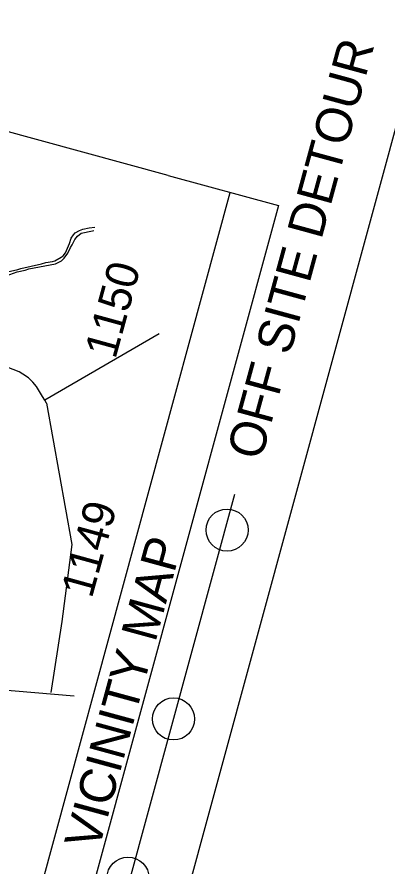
# Model space of a CAD drawing. Extents: x 2076126 to 2079903, y 925480 to 928006.
# Drawn here: x 2078865.6 to 2079033.1, y 926019.2 to 926403.1 of the extents above; entities that cross this region are included whole.
import ezdxf

# ---------------------------------------------------------------- set-up
doc = ezdxf.new("R2010")
doc.units = 0
for name, color, linetype in [('Default', 7, 'Continuous'), ('Old_Level_32', 7, 'Continuous'), ('Old_Level_59', 7, 'Continuous'), ('Old_Level_8', 7, 'Continuous'), ('Prop Roadway Bridge', 7, 'Continuous'), ('Prop Shade Heavy', 7, 'Continuous'), ('Prop Shade Light', 7, 'Continuous'), ('Sheet Title CELL', 7, 'Continuous')]:
    doc.layers.add(name, color=color, linetype=linetype)

msp = doc.modelspace()

# ---------------------------------------------------------------- linework, layer by layer
at = {"layer": 'Default'}
for p, q in [((2078934.09, 926331.41), (2078643.24, 926410.74)), ((2078934.09, 926331.41), (2078983.97, 926317.8)), ((2078845.04, 925894.23), (2078962.19, 926323.74)), ((2078983.97, 926317.8), (2078866.82, 925888.29))]:
    msp.add_line(p, q, dxfattribs=at)
at = {"layer": 'Old_Level_32'}
for p, q in [((2078879.02, 926228.42), (2078890.54, 926164.66)), ((2078890.54, 926164.66), (2078885.93, 926129.77)), ((2078885.93, 926129.77), (2078880.93, 926097.63))]:
    msp.add_line(p, q, dxfattribs=at)
for points in [[(2078878.26, 926229.88), (2078877.19, 926231.58), (2078874.53, 926236.04), (2078872.78, 926238.03), (2078870.88, 926239.9), (2078868.27, 926241.56), (2078866.69, 926242.59), (2078857.61, 926246.07), (2078843.96, 926251.15), (2078833.69, 926255.26), (2078827.41, 926257.54), (2078818.24, 926260.67), (2078813.77, 926262.12)], [(2078929.97, 926259.87), (2078878.26, 926229.88)], [(2078879.02, 926228.42), (2078878.26, 926229.88)], [(2078809.07, 926104.68), (2078812.81, 926104.24), (2078820.59, 926103.33), (2078824.79, 926102.73), (2078832.52, 926101.51), (2078836.21, 926100.88), (2078891.48, 926096.26)]]:
    msp.add_lwpolyline(points, dxfattribs=at)
at = {"layer": 'Old_Level_59'}
for points in [[(2078884.59, 926292.23), (2078885.77, 926292.91), (2078887.01, 926294.12), (2078888.59, 926296.24), (2078889.82, 926298.92), (2078890.58, 926300.07), (2078891.81, 926302.56), (2078893.03, 926304.05), (2078894.75, 926305.36), (2078899.77, 926306.41), (2078900.48, 926306.49)], [(2078890.22, 926303.08), (2078891.17, 926304.55), (2078891.95, 926305.43), (2078893.89, 926306.5), (2078895.41, 926307.09), (2078898.35, 926307.71), (2078900.89, 926307.99)], [(2078848.61, 926285.82), (2078855.38, 926286.95), (2078859.97, 926287.57), (2078866.02, 926288.89), (2078867.43, 926289.41), (2078876.71, 926291.54), (2078878.65, 926292.15), (2078881.75, 926292.49), (2078882.84, 926292.83), (2078885.66, 926294.48), (2078886.54, 926295.06), (2078887.58, 926296.51), (2078889.41, 926300.75), (2078890.22, 926303.08)], [(2078860.15, 926286.25), (2078862.46, 926286.72), (2078865.78, 926287.86), (2078869.31, 926288.64), (2078871.06, 926289.21), (2078883.03, 926291.52), (2078884.59, 926292.23)]]:
    msp.add_lwpolyline(points, dxfattribs=at)
at = {"layer": 'Prop Roadway Bridge'}
msp.add_lwpolyline([(2078921.55, 925929.3), (2079234.74, 927077.57), (2079619.8, 926972.54), (2079306.61, 925824.27)], close=True, dxfattribs=at)
at = {"layer": 'Prop Shade Heavy'}
msp.add_line((2078891.72, 925921.64), (2078964.21, 926187.41), dxfattribs=at)
at = {"layer": 'Prop Shade Light'}
for centre in [(2078960.72, 926171.12), (2078936.48, 926085.74), (2078915.88, 926013.75)]:
    msp.add_circle(centre, 9.52, dxfattribs=at)

# ---------------------------------------------------------------- texts
at = {"layer": 'Default'}
for s, p in [('OFF SITE DETOUR', (2078976.09, 926202.11)), ('VICINITY MAP', (2078902.55, 926025.81))]:
    msp.add_text(s, height=16.2199, rotation=74.7434, dxfattribs=at).set_placement(p)
at = {"layer": 'Old_Level_8'}
for s, p in [('1150', (2078910.15, 926248.02)), ('1149', (2078899.49, 926139.86))]:
    msp.add_text(s, height=14.598, rotation=74.6315, dxfattribs=at).set_placement(p)
at = {"layer": 'Sheet Title CELL'}
msp.add_text('TYPE OF WORK:', height=12.5001, rotation=74.7434, dxfattribs=at).set_placement((2078848.92, 926385.81))

doc.saveas('drawing.dxf')
